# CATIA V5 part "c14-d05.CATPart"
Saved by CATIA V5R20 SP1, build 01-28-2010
Part number: Part1
Bounding box of the stored display mesh (mm): x -55 to 55, y -96.632 to 96.632, z -25 to 65
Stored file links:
  D:\v5_r20\psrt_files_downloaded\c14\c14-catia-v5r20-figr-14-18\c14-d05.CATPart
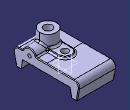
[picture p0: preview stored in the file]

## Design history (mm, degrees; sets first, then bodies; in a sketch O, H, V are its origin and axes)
Body1 (main body)
  Sketch1 on yz-plane, origin (0, 0, 0), H (0, 0, -1), V (0, 1, 0)
    construction line L1 (-49.4514, 0) -> (56.6299, 0)
    line L2 (0, 0) -> (0, 70.5918)
    point P3 (25, 75)
    line L3 (25, 75) -> (25, 90)
    point P4 (25, 90)
    line L4 (25, 90) -> (-25, 100)
    point P5 (-25, 100)
    line L5 (-25, 100) -> (-25, 0)
    point P6 (-25, 0)
    point P7 (0, 0)
    construction line L6 through (0, 0) direction (-1, 0)
    point P10 (25, -75)
    point P11 (25, -90)
    point P12 (-25, -100)
    point P13 (-25, 0)
    line L7 (0, 0) -> (0, -70.5918)
    line L8 (25, -75) -> (25, -90)
    line L9 (25, -90) -> (-25, -100)
    line L10 (-25, -100) -> (-25, 0)
    line L11 (25, 75) -> (0, 70.5918)
    point P14 (0, 70.5918)
    point P15 (0, -70.5918)
    point P16 (25, -75)
    line L12 (25, -75) -> (0, -70.5918)
    axis line L13 (25, 75) -> (-31.7388, 75)
    distance P5 P12 = 200
    length L3 = 15
    angle L11 L13 = 10
    distance L3 L5 = 50
    distance P3 P10 = 150
    angle L5 L6 = 270 (reference)
    coincidence: P6 L1, O P7, P6 P13, P10 P16
    symmetry: O P7 L1, P3 P10 L1, P4 P11 L1, P5 P12 L1, P6 P13 L1, L2 L7 L1, L3 L8 L1, L4 L9 L1, L5 L10 L1, P14 P15 L1, P3 P16 L1, L11 L12 L1
  Pad1: profile Sketch1, direction (1, 0, 0), length 55, mirrored extent
  Sketch2 on face of Pad1, origin (55, 0, 0), H (0, 1, 0), V (0, 0, 1)
    arc A1 centre (-50, 20) radius 20 from (-30.6351, 25) to (-69.3649, 25) ccw
    point P1 (-50, 20)
    line L1 (-69.3649, 25) -> (-30.6351, 25)
    reference projected line E1 (0, 25) -> (-100, 25) from edge [face of Pad1 | face of Pad1]
    reference projected point E2 (-100, 25) from vertex [face of Pad1 | face of Pad1 | face of Pad1]
    reference projected line E3 (0, 25) -> (-100, 25) from edge [face of Pad1 | face of Pad1]
    radius A1 = 20
    distance P1 E2 H = 50
    distance P1 E3 = 5
    horizontal: L1 H
    coincidence: L1 E1
  Pad2: profile Sketch2, direction (-1, 0, 0), length 55
  Sketch3 on face of Pad1, origin (0, 0, 25), H (1, 0, 0), V (0, 1, 0)
    circle A1 centre (0, -50) radius 25
    point P1 (0, -50)
    point P2 (0, -25)
    radius A1 = 25
    distance P1 H = 50
    coincidence: P1 V, A1 P2, P2 V
  Pad3: profile Sketch3, direction (0, 0, 1), length 40
  Sketch4 on face of Pad1, origin (0, 0, 25), H (1, 0, 0), V (0, 1, 0)
    line L1 (-20, -50) -> (-20, 0)
    point P2 (-20, 0)
    arc A1 centre (0, 0) radius 20 from (-20, 0) to (20, 0) cw
    point P3 (0, 0)
    line L2 (20, 0) -> (20, -50)
    line L3 (20, -50) -> (-20, -50)
    distance P3 L3 = 50
    radius A1 = 20
    coincidence: P2 H, P3 O
    vertical: L1 V, L2 V
    tangency: A1 L1, L2 A1
    horizontal: L3 H
  Pad4: profile Sketch4, direction (0, 0, 1), length 5
  Fillet1: radius 15, on edge [face of Pad1 | face of Pad1] (x2)
  Fillet2: radius 5, on edge [face of Pad1 | face of Pad4]
  Fillet3: radius 2, on edge [face of Pad4 | face of Fillet2]
  Fillet4: radius 5, on edge [face of Pad1 | face of Pad2]
  Fillet5: radius 5, on edge [face of Pad2 | face of Pad1]
  Fillet6: radius 5, on edge [face of Pad2 | face of Pad3]
  Fillet7: radius 2, on edge [face of Pad1 | face of Fillet1]; 1 edge
  Sketch5 on face of Pad1, origin (55, -45.7053, 34.0838), H (0, 1, 0), V (0, 0, 1)
    point P1 (-4.2947, -14.0838)
    reference projected arc E1 centre (-4.2947, -14.0838) radius 20 from (15.0702, -9.0838) to (-23.6596, -9.0838) ccw from edge of Pad2
    concentricity: P1 E1
  Hole1: placed by Sketch5, at (55, -50, 20) direction (-1, 0, 0), diameter 10, depth 20
  Sketch6 on face of Pad3, origin (0, -50, 65), H (1, 0, 0), V (0, 1, 0)
    point P1 (0, 0)
    reference projected circle E1 centre (0, 0) radius 25 from edge [face of Pad3 | face of Pad3]
    concentricity: P1 E1
  Hole2: placed by Sketch6, at (0, -50, 65) direction (0, 0, -1), diameter 25, through (limit type 3)
  Sketch7 on face of Pad4, origin (-2.136, -9.3115, 30), H (1, 0, 0), V (0, 1, 0)
    point P1 (2.136, 9.3115)
    reference projected arc E1 centre (2.136, 9.3115) radius 18.2918 from (20.4278, 9.3115) to (-16.1558, 9.3115) ccw from edge [face of Pad4 | face of Fillet3]
    concentricity: P1 E1
  Hole3: placed by Sketch7, at (0, 0, 30) direction (0, 0, -1), diameter 20, through (limit type 3)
